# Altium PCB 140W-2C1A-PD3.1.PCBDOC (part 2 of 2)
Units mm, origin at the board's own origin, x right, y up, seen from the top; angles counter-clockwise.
Board outline 57.13 x 21.16 mm, 6 copper layers (Top Layer, G02, P03, Mid-Layer 6, Mid-Layer 20, Bottom Layer), stack 1.489 mm thick; 81 components, 79 nets, 331 pads, 164 vias.
Unrouted connection lines stored in the file: 14.
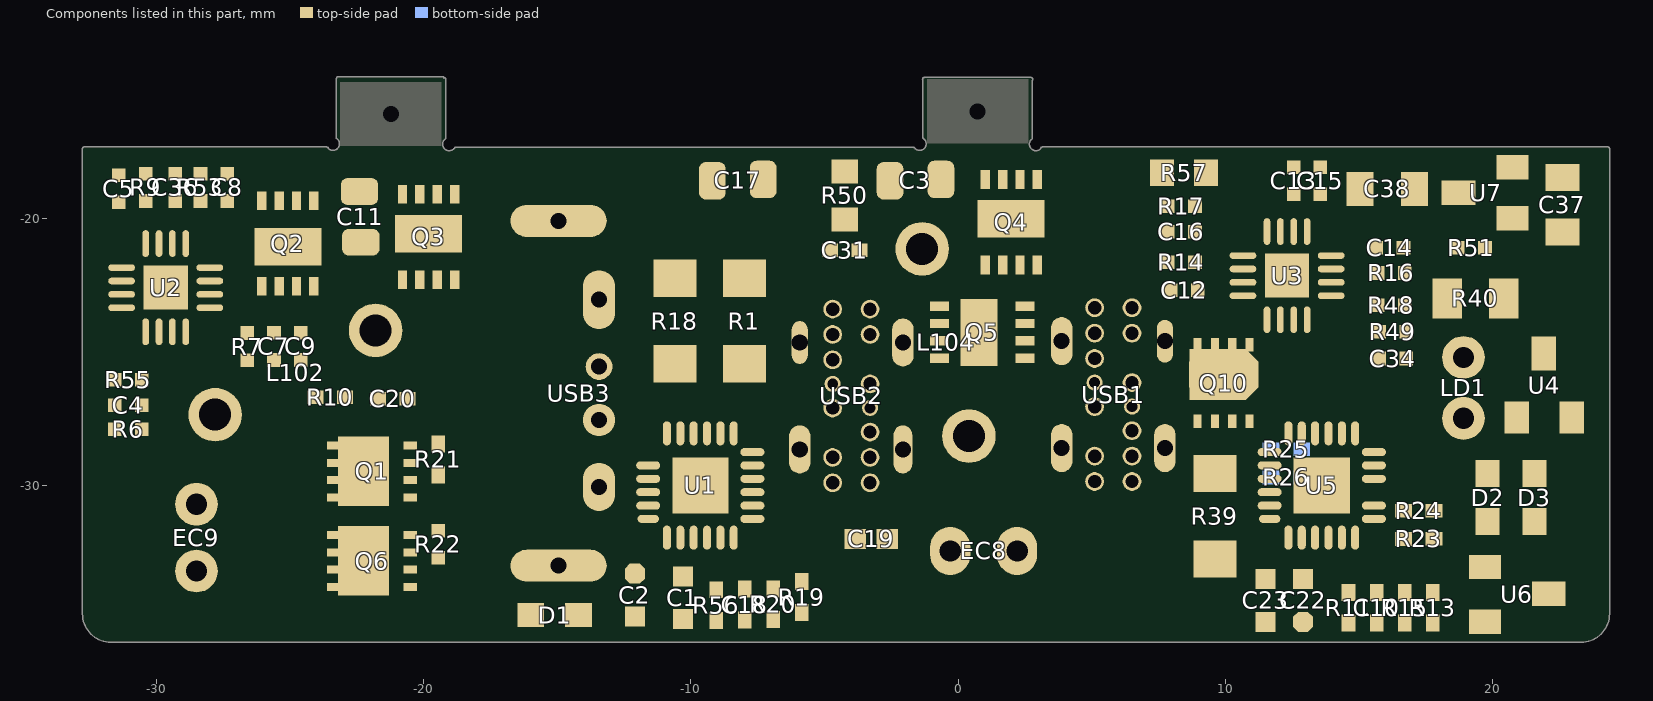
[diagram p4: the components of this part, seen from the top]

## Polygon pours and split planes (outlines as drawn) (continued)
NewNet3 on G02 "Top Layer-No Net" (solid, remove dead copper, pour order 1159): -32.764,-34.8 cw(c-32.7,-34.8) -32.764,-34.799 -32.764,-17.4 cw(c-32.7,-17.4) -32.7,-17.336 -23.625,-17.336 cw(c-23.625,-17.4) -23.561,-17.396 ccw(c-23.393,-17.22) -23.15,-17.22 ccw(c-23.393,-17.22) -23.253,-17.021 cw(c-23.224,-16.98) -23.275,-16.98 -23.275,-14.8 cw(c-23.224,-14.8) -23.25,-14.757 cw(c-23.2,-14.75) -23.2,-14.7 -19.3,-14.7 cw(c-19.3,-14.75) -19.25,-14.75 cw(c-19.3,-14.75) -19.25,-14.756 cw(c-19.225,-14.8) -19.175,-14.8 -19.175,-17 ccw(c-19.225,-17) -19.175,-16.999 -19.175,-17 cw(c-19.225,-17) -19.194,-17.04 ccw(c-19.045,-17.232) -18.846,-17.372 cw(c-18.805,-17.401) -18.805,-17.35 -1.683,-17.35 cw(c-1.675,-17.4) -1.635,-17.369 ccw(c-1.443,-17.22) -1.2,-17.22 ccw(c-1.443,-17.22) -1.303,-17.021 cw(c-1.274,-16.98) -1.325,-16.98 -1.325,-14.839 cw(c-1.274,-14.8) -1.274,-14.736 2.725,-14.736 cw(c2.725,-14.8) 2.789,-14.8 cw(c2.725,-14.8) 2.775,-14.839 2.775,-17 cw(c2.725,-17) 2.756,-17.04 ccw(c2.905,-17.232) 3.081,-17.399 cw(c3.145,-17.4) 3.145,-17.336 24.3,-17.336 cw(c24.3,-17.4) 24.364,-17.4 24.364,-34.8 cw(c24.3,-34.8) 24.364,-34.801 ccw(c23.3,-34.8) 24.364,-34.8 24.364,-34.801 cw(c23.3,-34.8) 23.301,-35.864 cw(c23.3,-35.8) 23.3,-35.864 -31.7,-35.864 cw(c-31.7,-34.8)
NewNet54 on G02 "NONET_L-01_P-001" (solid, remove dead copper, pour order 1154): -3.1,-28.4 -2.9,-28.6 -2.9,-29.1 -3.1,-29.3 -4.8,-29.3 -5.05,-29.05 -5.05,-28.6 -4.85,-28.4
NewNet54 on G02 "NONET_L-01_P-001" (solid, remove dead copper, pour order 1153): -5,-23.95 -3.05,-23.95 -2.85,-24.15 -2.85,-25.2 -3.1,-25.45 -4,-25.45 -4.15,-25.3 -4.15,-24.9 -4.35,-24.7 -5.05,-24.7 -5.15,-24.6 -5.15,-24.1
NewNet15 on G02 "NONET_L-01_P-001" (solid, remove dead copper, pour order 1152): 7.5,-27.65 7.95,-27.65 8.25,-27.95 8.25,-29.95 7.6,-30.6 3.95,-30.6 3.3,-29.95 3.3,-23.7 4.2,-22.8 6.8,-22.8 6.95,-22.95 6.95,-23.5 6.8,-23.65 4.85,-23.65 4.4,-24.1 4.4,-29.25 4.7,-29.55 7.05,-29.55 7.35,-29.25 7.35,-27.8
NewNet8 on G02 "NONET_L-01_P-001" (solid, remove dead copper, pour order 1151): 4.7,-28.05 5.05,-27.7 5.85,-27.7 6,-27.85 6,-28.2 6.25,-28.45 6.9,-28.45 7.1,-28.65 7.1,-29.2 6.9,-29.4 4.85,-29.4 4.7,-29.25
NewNet8 on G02 "NONET_L-01_P-001" (solid, remove dead copper, pour order 1150): 6.95,-24.05 6.7,-23.8 5.05,-23.8 4.75,-24.1 4.75,-24.5 5,-24.75 6.75,-24.75 6.95,-24.55
NewNet21 on G02 "Top Layer-NewNet4" (solid, remove dead copper, pour order 1134): -1.2,-14.95 -1.2,-17.35 -1.9,-18.05 -3.15,-19.3 -3.65,-19.3 -4.2,-19.3 -4.4,-19.1 -5.1,-18.4 -5.1,-18 -5.35,-17.75 -5.9,-17.75 -7.15,-17.75 -7.35,-17.95 -8,-18.6 -8,-19.85 -8,-20.55 -7.85,-20.7 -7.25,-21.3 -5.8,-21.3 -3.1,-21.3 -1.95,-20.15 -1.85,-20.05 4.55,-20.05 5.05,-20.05 5.85,-19.25 5.95,-19.15 5.95,-17.7 2.75,-17.7 2.4,-17.35 2.4,-15 2.25,-14.85
NewNet6 on G02 "Top Layer-NewNet4" (solid, remove dead copper, pour order 1133): -6.45,-25.3 -6.45,-23.35 -6.05,-22.95 -5.85,-22.75 -4.05,-22.75 -2.6,-22.75 -1.7,-23.65 -1.55,-23.8 -1.55,-27.55 -1.55,-29.75 -2.2,-30.4 -2.35,-30.55 -4.65,-30.55 -5.15,-30.55 -6,-29.7 -6.25,-29.45 -6.25,-28.05 -6.25,-27.75 -6.15,-27.65 -5.7,-27.65 -5.45,-27.9 -5.4,-27.95 -5.4,-28.35 -5.4,-29.1 -5.1,-29.4 -4.95,-29.55 -4.25,-29.55 -2.9,-29.55 -2.6,-29.25 -2.6,-24.1 -2.85,-23.85 -2.95,-23.75 -3.5,-23.75 -5.15,-23.75 -5.4,-24 -5.45,-24.05 -5.45,-24.7 -5.45,-25.3 -5.6,-25.45 -5.65,-25.5 -6.05,-25.5 -6.35,-25.5 -6.45,-25.4 -6.45,-25.3
no net on G02 " " (hatched Horizontal grid 0.102 track 0.127, remove dead copper, pour order 1114): -87.607,-3.853
no net on G02 " " (hatched Horizontal grid 0.102 track 0.127, remove dead copper, pour order 1111): -63.107,-28.947
no net on G02 " " (hatched Horizontal grid 0.102 track 0.127, remove dead copper, pour order 1110): -62.643,-28.643
no net on G02 " " (hatched Horizontal grid 0.102 track 0.127, remove dead copper, pour order 1103): -82.407,-24.579
no net on G02 " " (hatched Horizontal grid 0.102 track 0.127, remove dead copper, pour order 1102): -46.707,-22.871
no net on G02 " " (hatched Horizontal grid 0.102 track 0.127, remove dead copper, pour order 1101): -63.085,-23.452
no net on G02 "    " (hatched Horizontal grid 0.102 track 0.127, remove dead copper, pour order 1083): -83.607,-32.952
no net on G02 "   " (hatched Horizontal grid 0.102 track 0.127, remove dead copper, pour order 1077): -83.407,-23.852
no net on G02 "   " (hatched Horizontal grid 0.102 track 0.127, remove dead copper, pour order 1076): -83.507,-23.317
no net on G02 "   " (hatched Horizontal grid 0.102 track 0.127, remove dead copper, pour order 1072): -95.307,-16.146
no net on G02 "   " (hatched Horizontal grid 0.102 track 0.127, remove dead copper, pour order 1071): -95.657,-15.552
no net on G02 "    " (hatched Horizontal grid 0.102 track 0.127, remove dead copper, pour order 1063): -83.007,-23.652
no net on G02 "    " (hatched Horizontal grid 0.102 track 0.127, remove dead copper, pour order 1062): -69.507,-27.052
no net on G02 "    " (hatched Horizontal grid 0.102 track 0.127, remove dead copper, pour order 1061): -65.007,-28.652
no net on G02 "    " (hatched Horizontal grid 0.102 track 0.127, remove dead copper, pour order 1060): -71.407,-22.852
no net on G02 "    " (hatched Horizontal grid 0.102 track 0.127, remove dead copper, pour order 1059): -71.407,-22.452
no net on G02 "    " (hatched Horizontal grid 0.102 track 0.127, remove dead copper, pour order 1058): -71.407,-21.052
no net on G02 "    " (hatched Horizontal grid 0.102 track 0.127, remove dead copper, pour order 1057): -71.807,-20.952
no net on G02 "G02-No Net" (hatched Horizontal grid 0.102 track 0.127, remove dead copper, pour order 1028): -71.407,-13.552
no net on G02 "G02-No Net 1" (hatched Horizontal grid 0.102 track 0.127, remove dead copper, pour order 1027): -71.707,-13.452
NewNet3 on P03 "Top Layer-No Net" (solid, remove dead copper, pour order 1160): -32.764,-34.8 cw(c-32.7,-34.8) -32.764,-34.799 -32.764,-17.4 cw(c-32.7,-17.4) -32.7,-17.336 -23.625,-17.336 cw(c-23.625,-17.4) -23.561,-17.396 ccw(c-23.393,-17.22) -23.15,-17.22 ccw(c-23.393,-17.22) -23.253,-17.021 cw(c-23.224,-16.98) -23.275,-16.98 -23.275,-14.8 cw(c-23.224,-14.8) -23.25,-14.757 cw(c-23.2,-14.75) -23.2,-14.7 -19.3,-14.7 cw(c-19.3,-14.75) -19.25,-14.75 cw(c-19.3,-14.75) -19.25,-14.756 cw(c-19.225,-14.8) -19.175,-14.8 -19.175,-17 ccw(c-19.225,-17) -19.175,-16.999 -19.175,-17 cw(c-19.225,-17) -19.194,-17.04 ccw(c-19.045,-17.232) -18.846,-17.372 cw(c-18.805,-17.401) -18.805,-17.35 -1.683,-17.35 cw(c-1.675,-17.4) -1.635,-17.369 ccw(c-1.443,-17.22) -1.2,-17.22 ccw(c-1.443,-17.22) -1.303,-17.021 cw(c-1.274,-16.98) -1.325,-16.98 -1.325,-14.839 cw(c-1.274,-14.8) -1.274,-14.736 2.725,-14.736 cw(c2.725,-14.8) 2.789,-14.8 cw(c2.725,-14.8) 2.775,-14.839 2.775,-17 cw(c2.725,-17) 2.756,-17.04 ccw(c2.905,-17.232) 3.081,-17.399 cw(c3.145,-17.4) 3.145,-17.336 24.3,-17.336 cw(c24.3,-17.4) 24.364,-17.4 24.364,-34.8 cw(c24.3,-34.8) 24.364,-34.801 ccw(c23.3,-34.8) 24.364,-34.8 24.364,-34.801 cw(c23.3,-34.8) 23.301,-35.864 cw(c23.3,-35.8) 23.3,-35.864 -31.7,-35.864 cw(c-31.7,-34.8)
NewNet15 on P03 "NONET_L-01_P-001" (solid, remove dead copper, pour order 1156): 7.2,-23 8.15,-23.95 8.15,-29.25 7.2,-30.2 4.4,-30.2 3.45,-29.25 3.45,-23.95 4.4,-23
NewNet6 on P03 "NONET_L-01_P-001" (solid, remove dead copper, pour order 1155): -6.35,-23.8 -5.6,-23.05 -2.4,-23.05 -1.65,-23.8 -1.65,-29.5 -2.4,-30.25 -5.6,-30.25 -6.35,-29.5
NewNet54 on P03 "NONET_L-01_P-001" (solid, remove dead copper, pour order 1148): -3.05,-29.45 -4.9,-29.45 -5.1,-29.25 -5.1,-28.55 -4.7,-28.15 -3.95,-28.15 -3.55,-28.55 -3.05,-28.55 -2.85,-28.75 -2.85,-29.25
NewNet54 on P03 "NONET_L-01_P-001" (solid, remove dead copper, pour order 1147): -5,-23.85 -3.15,-23.85 -2.95,-24.05 -2.95,-25.05 -3.25,-25.35 -3.9,-25.35 -4.5,-24.75 -5,-24.75 -5.2,-24.55 -5.2,-24.05
NewNet8 on P03 "NONET_L-01_P-001" (solid, remove dead copper, pour order 1146): 6.85,-29.4 7,-29.25 7,-28.8 6.8,-28.6 6.35,-28.6 5.95,-28.2 5.95,-27.8 5.75,-27.6 4.95,-27.6 4.6,-27.95 4.6,-29.2 4.8,-29.4
NewNet8 on P03 "NONET_L-01_P-001" (solid, remove dead copper, pour order 1145): 4.85,-23.85 6.7,-23.85 6.9,-24.05 6.9,-25.05 6.6,-25.35 5.95,-25.35 5.35,-24.75 4.85,-24.75 4.65,-24.55 4.65,-24.05
no net on P03 " " (hatched Horizontal grid 0.102 track 0.127, remove dead copper, pour order 1115): -84.907,-7.206
no net on P03 " " (hatched Horizontal grid 0.102 track 0.127, remove dead copper, pour order 1108): -82.307,-24.478
no net on P03 " " (hatched Horizontal grid 0.102 track 0.127, remove dead copper, pour order 1107): -45.007,-24.478
no net on P03 " " (hatched Horizontal grid 0.102 track 0.127, remove dead copper, pour order 1106): -59.507,-33.768
no net on P03 " " (hatched Horizontal grid 0.102 track 0.127, remove dead copper, pour order 1105): -46.002,-22.452
no net on P03 " " (hatched Horizontal grid 0.102 track 0.127, remove dead copper, pour order 1104): -45.494,-22.452
no net on P03 " " (hatched Horizontal grid 0.102 track 0.127, remove dead copper, pour order 1094): -59.207,-11.27
no net on P03 " " (hatched Horizontal grid 0.102 track 0.127, remove dead copper, pour order 1085): -82.707,-24.681
no net on P03 " " (hatched Horizontal grid 0.102 track 0.127, remove dead copper, pour order 1084): -81.407,-22.039
no net on P03 "    " (hatched Horizontal grid 0.102 track 0.127, remove dead copper, pour order 1067): -58.107,-5.986
no net on P03 "    " (hatched Horizontal grid 0.102 track 0.127, remove dead copper, pour order 1066): -67.957,-3.402
no net on P03 "              " (hatched Horizontal grid 0.102 track 0.127, remove dead copper, pour order 1065): -96.007,-15.952
no net on P03 "    " (hatched Horizontal grid 0.102 track 0.127, remove dead copper, pour order 1053): -56.407,-5.952
NewNet3 on Bottom Layer "Top Layer-No Net" (solid, remove dead copper, pour order 1161): -32.764,-34.8 cw(c-32.7,-34.8) -32.764,-34.799 -32.764,-17.4 cw(c-32.7,-17.4) -32.7,-17.336 -23.625,-17.336 cw(c-23.625,-17.4) -23.561,-17.396 ccw(c-23.393,-17.22) -23.15,-17.22 ccw(c-23.393,-17.22) -23.253,-17.021 cw(c-23.224,-16.98) -23.275,-16.98 -23.275,-14.8 cw(c-23.224,-14.8) -23.25,-14.757 cw(c-23.2,-14.75) -23.2,-14.7 -19.3,-14.7 cw(c-19.3,-14.75) -19.25,-14.75 cw(c-19.3,-14.75) -19.25,-14.756 cw(c-19.225,-14.8) -19.175,-14.8 -19.175,-17 ccw(c-19.225,-17) -19.175,-16.999 -19.175,-17 cw(c-19.225,-17) -19.194,-17.04 ccw(c-19.045,-17.232) -18.846,-17.372 cw(c-18.805,-17.401) -18.805,-17.35 -1.683,-17.35 cw(c-1.675,-17.4) -1.635,-17.369 ccw(c-1.443,-17.22) -1.2,-17.22 ccw(c-1.443,-17.22) -1.303,-17.021 cw(c-1.274,-16.98) -1.325,-16.98 -1.325,-14.839 cw(c-1.274,-14.8) -1.274,-14.736 2.725,-14.736 cw(c2.725,-14.8) 2.789,-14.8 cw(c2.725,-14.8) 2.775,-14.839 2.775,-17 cw(c2.725,-17) 2.756,-17.04 ccw(c2.905,-17.232) 3.081,-17.399 cw(c3.145,-17.4) 3.145,-17.336 24.3,-17.336 cw(c24.3,-17.4) 24.364,-17.4 24.364,-34.8 cw(c24.3,-34.8) 24.364,-34.801 ccw(c23.3,-34.8) 24.364,-34.8 24.364,-34.801 cw(c23.3,-34.8) 23.301,-35.864 cw(c23.3,-35.8) 23.3,-35.864 -31.7,-35.864 cw(c-31.7,-34.8)
NewNet15 on Bottom Layer "NONET_L-01_P-001" (solid, remove dead copper, pour order 1149): 3.35,-23.85 4.3,-22.9 7.35,-22.9 8.35,-23.9 8.35,-30.05 7.6,-30.8 4.15,-30.8 3.35,-30
NewNet21 on Bottom Layer "Top Layer-NewNet4" (solid, remove dead copper, pour order 1143): -7.1,-17.75 -5.4,-17.75 -5.25,-17.9 -5.15,-18 -5.15,-18.65 -4.6,-19.2 -4.45,-19.35 -3.3,-19.35 -3.25,-19.35 -2.65,-18.75 -1.55,-17.65 -1.45,-17.65 -1.15,-17.35 -1.15,-15.8 -1.15,-14.9 -1,-14.75 2.55,-14.75 2.7,-14.9 2.7,-17.35 2.9,-17.55 3.3,-17.55 5.7,-17.55 6.1,-17.95 6.15,-18 6.15,-19.6 6.15,-19.7 6.55,-20.1 5.8,-20.85 4.85,-20.85 0.3,-20.85 -0.3,-20.25 -0.6,-19.95 -1.6,-19.95 -1.75,-19.95 -2.4,-20.6 -3,-21.2 -6,-21.2 -7.15,-21.2 -7.5,-20.85 -7.55,-20.8 -7.55,-19.2 -7.55,-18.1 -7.15,-17.7
NewNet6 on Bottom Layer "Top Layer-NewNet4" (solid, remove dead copper, pour order 1141): -6.4,-29.05 -6.4,-23.35 -6.05,-23 -5.7,-22.65 -4.2,-22.65 -2.15,-22.65 -1.85,-22.95 -1.25,-23.55 -1.25,-24.65 -1.25,-28.95 -1.95,-29.65 -2,-29.6 -2.35,-29.6 -2.5,-29.45 -2.5,-28.8 -2.5,-24 -2.75,-23.75 -2.8,-23.7 -3.3,-23.7 -5,-23.7 -5.25,-23.95 -5.45,-24.15 -5.45,-24.7 -5.45,-29.25 -5.7,-29.5 -5.8,-29.6 -6.1,-29.6 -6.15,-29.6 -6.4,-29.35
NewNet61 on Bottom Layer "Top Layer-NewNet4" (solid, remove dead copper, pour order 1140): -16.75,-32.4 -16.6,-32.25 -15.65,-32.25 -15,-32.25 -14.8,-32.05 -14.65,-31.9 -14.65,-31.5 -14.65,-31.25 -15.1,-30.8 -15.1,-30.75 -15.1,-22.4 -14.4,-21.7 -14.35,-21.65 -13.15,-21.65 -12.7,-22.1 -12.7,-22.5 -12.7,-23.8 -12.95,-24.05 -13.1,-24.2 -13.45,-24.2 -13.7,-24.2 -14.25,-24.75 -14.35,-24.85 -14.35,-25.25 -14.35,-30.7 -13.9,-31.15 -13.1,-31.95 -13.1,-33 -13.1,-33.2 -13.35,-33.45 -13.55,-33.65 -13.65,-33.65 -16.25,-33.65 -16.75,-33.15 -16.8,-33.1 -16.8,-32.85 -16.8,-32.45
NewNet54 on Bottom Layer "Top Layer-NewNet4" (solid, remove dead copper, pour order 1139): -19.85,-32.3 -17.95,-32.3 -17.75,-32.5 -17.2,-33.05 -17.2,-33.15 -17.2,-33.25 -16.9,-33.55 -16.65,-33.8 -15.8,-33.8 -6.35,-33.8 -5.3,-32.75 -5.1,-32.55 -5.1,-29.95 -5.1,-28.6 -5,-28.5 -4.3,-27.8 -4.3,-27.15 -4.3,-25.1 -4.55,-24.85 -5,-24.4 -5,-24.05 -5.05,-24 -4.95,-23.9 -4.85,-23.9 -3.05,-23.9 -3,-23.95 -2.75,-24.2 -2.75,-25.25 -2.85,-25.35 -3.05,-25.55 -3.2,-25.55 -3.35,-25.55 -3.55,-25.75 -3.75,-25.95 -3.75,-26.55 -3.75,-28.25 -3.55,-28.45 -3.45,-28.55 -3.1,-28.55 -2.95,-28.55 -2.75,-28.75 -1.85,-29.65 -1.85,-33.55 -3.05,-34.75 -4.05,-35.75 -6.3,-35.75 -19.1,-35.75 -19.5,-35.35 -20.05,-34.8 -20.05,-34.05 -20.05,-32.55 -19.8,-32.3
NewNet8 on Bottom Layer "Top Layer-NewNet4" (solid, remove dead copper, pour order 1138): 6.8,-28.45 6.3,-28.45 6,-28.15 6,-25.65 6.45,-25.2 6.9,-24.75 6.9,-24.25 6.9,-24.05 6.75,-23.9 6.5,-23.9 4.85,-23.9 4.7,-24.05 4.7,-24.4 4.9,-24.6 4.95,-24.65 5.15,-24.65 5.3,-24.65 5.5,-24.85 5.5,-25.8 5.5,-27.5 4.85,-28.15 4.6,-28.4 4.6,-29 4.6,-29.15 4.75,-29.3 5.2,-29.3 6.75,-29.3 6.9,-29.15 7,-29.05 7,-28.8 7,-28.6 6.85,-28.45
no net on Bottom Layer " " (hatched Horizontal grid 0.102 track 0.127, remove dead copper, pour order 1116): -68.607,-15.029
no net on Bottom Layer " " (hatched Horizontal grid 0.102 track 0.127, remove dead copper, pour order 1109): -87.007,-29.862
no net on Bottom Layer " " (hatched Horizontal grid 0.102 track 0.127, remove dead copper, pour order 1096): -44.007,-20.152
no net on Bottom Layer " " (hatched Horizontal grid 0.102 track 0.127, remove dead copper, pour order 1095): -91.808,-14.756
no net on Bottom Layer " " (hatched Horizontal grid 0.102 track 0.127, remove dead copper, pour order 1092): -58.355,-8.831
no net on Bottom Layer " " (hatched Horizontal grid 0.102 track 0.127, remove dead copper, pour order 1091): -48.982,-7.852
no net on Bottom Layer " " (hatched Horizontal grid 0.102 track 0.127, remove dead copper, pour order 1090): -50.107,-7.998
no net on Bottom Layer " " (hatched Horizontal grid 0.102 track 0.127, remove dead copper, pour order 1089): -54.507,-12.912
no net on Bottom Layer " " (hatched Horizontal grid 0.102 track 0.127, remove dead copper, pour order 1088): -54.207,-12.952
no net on Bottom Layer " " (hatched Horizontal grid 0.102 track 0.127, remove dead copper, pour order 1087): -55.268,-13.052
no net on Bottom Layer " " (hatched Horizontal grid 0.102 track 0.127, remove dead copper, pour order 1086): -51.107,-28.034
no net on Bottom Layer "              " (hatched Horizontal grid 0.102 track 0.127, remove dead copper, pour order 1064): -67.107,-6.452
no net on Bottom Layer "    " (hatched Horizontal grid 0.102 track 0.127, remove dead copper, pour order 1054): -40.707,-19.452
no net on Bottom Layer "  " (hatched Horizontal grid 0.102 track 0.127, remove dead copper, pour order 1033): -43.707,-3.852
no net on Bottom Layer "  " (hatched Horizontal grid 0.102 track 0.127, remove dead copper, pour order 1032): -49.307,-5.652
no net on Bottom Layer "Bottom Layer-No Net" (hatched Horizontal grid 0.102 track 0.127, remove dead copper, pour order 1031): -84.507,-17.452
no net on Bottom Layer "Bottom Layer-No Net 1" (hatched Horizontal grid 0.102 track 0.127, remove dead copper, pour order 1030): -89.007,-32.052
no net on Bottom Layer "Bottom Layer-No Net 2" (hatched Horizontal grid 0.102 track 0.127, remove dead copper, pour order 1029): -89.007,-32.052
no net on Bottom Layer "Bottom Layer-No Net 3" (hatched Horizontal grid 0.102 track 0.127, remove dead copper, pour order 1026): -106.507,-12.752

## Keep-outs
Keep-Out Layer:
  lines w0.1: -23.625,-17.4 ccw(c-23.393,-17.22) -23.224,-16.98 -23.224,-14.8 ; -23.2,-14.75 -19.3,-14.75 -19.25,-14.8 ; -19.225,-14.8 -19.225,-17 ccw(c-19.045,-17.232) -18.805,-17.401 -1.675,-17.401 ccw(c-1.443,-17.22) -1.274,-16.98 -1.274,-14.8 ; 2.725,-14.8 2.725,-17 ccw(c2.905,-17.232) 3.145,-17.401
  lines w0.127: -23.625,-17.4 -32.7,-17.4 -32.7,-34.8 ccw(c-31.7,-34.8) -31.7,-35.8 23.3,-35.8 ccw(c23.3,-34.8) 24.3,-34.8 24.3,-17.4 3.145,-17.4 ; 0.725,-14.8 2.725,-14.8 0.725,-14.8 ; 0.725,-14.8 -1.274,-14.8 0.725,-14.8

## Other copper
Top Layer:
  pour cut-out: 14.869,-28.908 14.869,-31.092 15.05,-30.912 15.05,-28.97 14.84,-28.76
  region net NewNet59: -14.6,-26.8 -14.75,-26.95 -14.75,-27.95 -14.6,-28.1 -12.95,-28.1 -12.75,-27.9 -12.75,-27.05 -13,-26.8
  region net NewNet60: -14.5,-24.8 -13.1,-24.8 -12.85,-25.05 -12.85,-26 -13.05,-26.2 -14.55,-26.2 -14.7,-26.05 -14.7,-25
  pour cut-out: -9.688,-24.713 -9.025,-24.05 -8.65,-24.05 -8.65,-24.55 -9.3,-25.2 -9.85,-25.2
  pour cut-out: -7.2,-29.5 -7.05,-29.65 -6.15,-29.65 -5.8,-30 -5.5,-30 -5.15,-30.35 -5.15,-30.85 -5.3,-31 -6,-31 -6.25,-30.75 -6.95,-30.75 -7.2,-30.5 -8.2,-30.5 -8.4,-30.3 -8.4,-29.65 -8.25,-29.5
G02:
  pour cut-out: 9.95,-31.5 10.15,-31.7 14.1,-31.7 16.15,-29.65 16.9,-29.65 16.95,-29.7 16.95,-30.35 16.8,-30.5 15.95,-30.5 14.25,-32.2 9.9,-32.2 9.85,-32.25 9.3,-32.25 9.15,-32.1 9.15,-31.6 9.25,-31.5
P03:
  pour cut-out: -6.1,-30.3 -7.1,-30.3 -8.5,-28.9 -8.5,-24.85 -8.25,-24.6 -8.25,-23.95 -8.4,-23.8 -8.9,-23.8 -9.15,-24.05 -9.1,-24.1 -9.1,-29.05 -7.4,-30.75 -6.15,-30.75 -5.9,-31 -5.8,-30.9 -5.4,-30.9
  pour cut-out: -7.45,-24.3 -6.85,-24.9 -6.85,-28.8 -7.2,-29.15 -7.2,-29.6 -6.95,-29.85 -6.6,-29.85 -6.3,-30.15 -6.45,-30.3 -7.2,-30.3 -7.75,-29.75 -7.75,-28.8 -7.35,-28.4 -7.35,-25.15 -7.95,-24.55 -7.95,-24.35
Multi-Layer:
  pour cut-out: 9.25,-31.45 9.85,-31.45 10,-31.6 10,-32 9.8,-32.2 9.35,-32.2 9.15,-32 9.15,-31.55
  pour cut-out: 16.7,-29.6 16.85,-29.75 16.85,-30.25 16.65,-30.45 16.15,-30.45 16,-30.3 16,-29.75 16.15,-29.6
  pour cut-out: -7.7,-23.75 -7.4,-24.05 -7.4,-24.55 -7.6,-24.75 -9.05,-24.75 -9.25,-24.55 -9.25,-24 -9,-23.75
  pour cut-out: -6.05,-29.7 -5.7,-30.05 -5.5,-30.05 -5.2,-30.35 -5.2,-30.85 -5.3,-30.95 -5.9,-30.95 -6.3,-30.55 -6.55,-30.55 -6.8,-30.3 -6.8,-29.8 -6.7,-29.7

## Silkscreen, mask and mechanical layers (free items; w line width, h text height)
Top Overlay:
  lines w0.102: -27.2,-17.9 -26.9,-17.6 -26.85,-17.6 -23.95,-17.6 ; -16.85,-32.15 -13.25,-32.15 -12.75,-32.65 -11.65,-32.65 ; -5.55,-35.75 -5.8,-35.5 ; -5.55,-35.25 -5.8,-35.5 ; -3.35,-19.65 -3.5,-19.8 -2,-19.8 ; -2.9,-35.5 -5.8,-35.5 ; 0.15,-20.3 0.15,-19.3 ; 6.55,-34.1 10.65,-34.1 10.35,-33.8 ; 10.6,-17.75 12.3,-17.75 ; 11.95,-17.5 12.2,-17.75 ; 16.25,-26 16.4,-25.85 16.4,-28.3 16.45,-28.35 ; 17.15,-21.1 17.35,-21.1 17.6,-20.85 17.6,-21 ; 18.45,-28.85 18.45,-30.35 18.6,-30.2 ; 20.65,-20.75 20.65,-20.45 ; 21,-20.45 20.65,-20.45 ; 21.8,-23.05 21.8,-21.6 20.65,-20.45 ; -5.8,-35.5 -5.8,-35.5 ; -5.8,-35.5 -5.8,-35.5 ; -5.8,-35.5 -5.8,-35.5 ; 12.2,-17.75 12.2,-17.75
  text "V-" at -21.9,-14.15 h2
  text "V+" at 0.9,-14.3 h2
Bottom Overlay:
  lines w0.127: -12.525,-33.175 -17.475,-33.175 cw(c-17.475,-32.775) -17.875,-32.775 -17.875,-20.425 cw(c-17.475,-20.425) -17.475,-20.025 -12.525,-20.025 cw(c-12.525,-20.425) -12.125,-20.425 -12.125,-32.775 ; -12.525,-32.875 -17.475,-32.875 cw(c-17.475,-32.775) -17.575,-32.775 -17.575,-20.425 cw(c-17.475,-20.425) -17.475,-20.325 -12.525,-20.325 cw(c-12.525,-20.425) -12.425,-20.425 -12.425,-32.775 ; 5.5,-31.07 cw(c5.5,-29.79) 4.22,-29.79 4.22,-23.41 cw(c5.5,-23.41) 5.5,-22.13 6.1,-22.13 cw(c6.1,-23.41) 7.38,-23.41 ; 5.5,-30.87 cw(c5.5,-29.79) 4.42,-29.79 4.42,-23.41 cw(c5.5,-23.41) 5.5,-22.33 6.1,-22.33 cw(c6.1,-23.41) 7.18,-23.41 ; 6.1,-31.07 ccw(c6.1,-29.79) 7.38,-29.79 ; 6.1,-30.87 ccw(c6.1,-29.79) 7.18,-29.79 ; -15.395,-32.05 -15.395,-21.15 ; -15.395,-32.05 -14.895,-31.55 ; -15.395,-32.05 -13.245,-32.05 ; -15.395,-21.15 -13.245,-21.15 ; -15.395,-21.15 -14.895,-21.65 ; -14.895,-31.55 -14.895,-21.65 ; -14.895,-31.55 -13.745,-31.55 ; -14.895,-21.65 -13.745,-21.65 ; -13.745,-31.55 -13.245,-32.05 ; -13.745,-31.55 -13.745,-21.65 ; -13.745,-21.65 -13.245,-21.15 ; -13.245,-32.05 -13.245,-21.15 ; -5.58,-29.79 ccw(c-4.3,-29.79) -4.3,-31.07 -3.7,-31.07 ccw(c-3.7,-29.79) -2.42,-29.79 -2.42,-23.41 ccw(c-3.7,-23.41) -3.7,-22.13 -4.3,-22.13 ccw(c-4.3,-23.41) -5.58,-23.41 -5.58,-29.79 ; -5.38,-29.79 ccw(c-4.3,-29.79) -4.3,-30.87 -3.7,-30.87 ccw(c-3.7,-29.79) -2.62,-29.79 -2.62,-23.41 ccw(c-3.7,-23.41) -3.7,-22.33 -4.3,-22.33 ccw(c-4.3,-23.41) -5.38,-23.41 -5.38,-29.79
